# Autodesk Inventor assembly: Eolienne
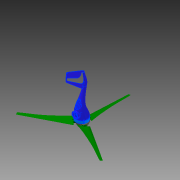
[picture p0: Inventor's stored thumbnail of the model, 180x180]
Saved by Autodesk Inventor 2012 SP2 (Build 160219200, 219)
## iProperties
Created: 2014-09
Part Number: Eolienne
Document SubType Name: Assembly
Designer: papa
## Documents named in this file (6)
- F:\Consmec\1si\TP\Energis-Eolienne\BAC PRO - SI\Dossier technique\Mécanisme modèle numérique\Composants importés\Eolienne\Eolienne.iam
- F:\Consmec\1si\TP\Energis-Eolienne\BAC PRO - SI\Dossier technique\Mécanisme modèle numérique\Composants importés\Eolienne\Corps.iam
- F:\Consmec\1si\TP\Energis-Eolienne\BAC PRO - SI\Dossier technique\Mécanisme modèle numérique\Composants importés\Eolienne\Hélice.iam
- F:\Consmec\1si\TP\Energis-Eolienne\BAC PRO - SI\Dossier technique\Mécanisme modèle numérique\Composants importés\Eolienne\Guidage arbre.iam
- F:\Consmec\1si\TP\Energis-Eolienne\BAC PRO - SI\Dossier technique\Mécanisme modèle numérique\Composants importés\Eolienne\Liaison mât.iam
- F:\Consmec\1si\TP\Energis-Eolienne\BAC PRO - SI\Dossier technique\Mécanisme modèle numérique\Composants importés\Eolienne\B18.2.4.5M - Hex jam nut,  M16 x 2 --D-_PreviewCfg.ipt
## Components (5 placed, 5 different names)
1. Corps:1 [sub-assembly]
2. Hélice:1 [sub-assembly]
3. Guidage arbre:1 [sub-assembly]
4. Liaison mât:1 [sub-assembly]
5. B18.2.4.5M - Hex jam nut,  M16 x 2 --D-:1
